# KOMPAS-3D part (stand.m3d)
File: created 18.09.2016 11:59:09, last saved 19.09.2016 14:49:05.
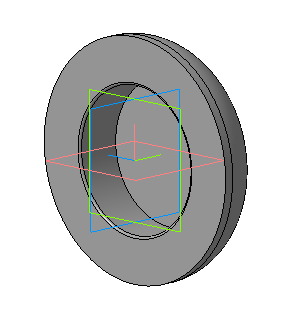
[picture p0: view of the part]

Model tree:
1. Эскиз:1
2. Операция вращения:1
     Угол 1 = 360
3. Эскиз:2
4. Операция выдавливания:1
     Расстояние 1 = 5
5. Скругление:1
     Радиус = 2
6. Скругление:2
     Радиус = 1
